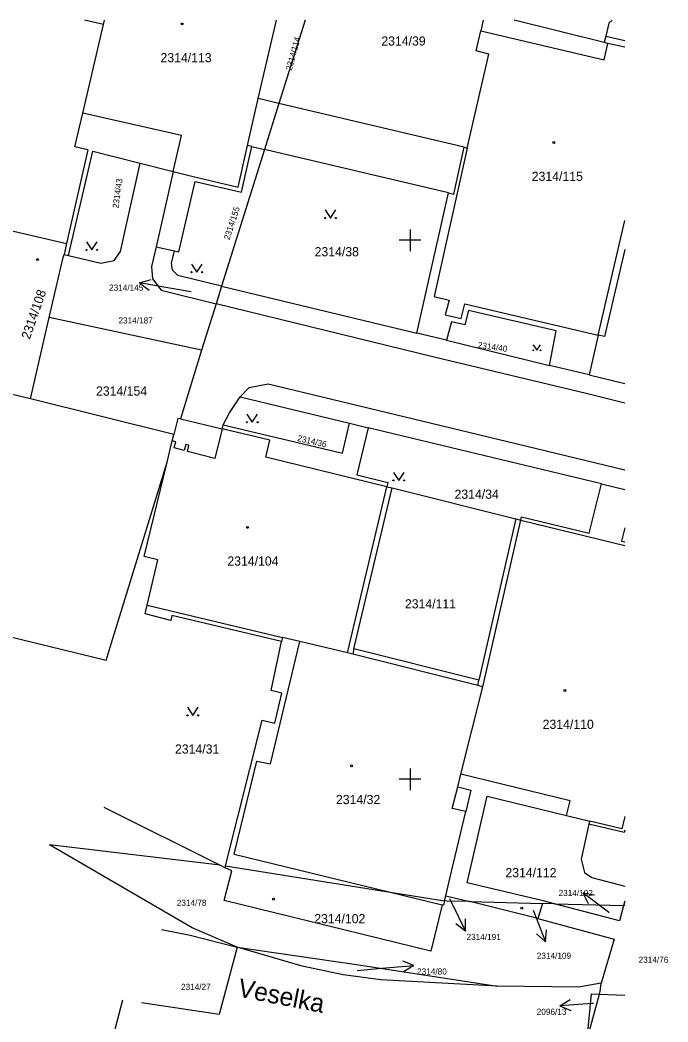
# Model space of a CAD drawing. Extents: x -599866 to -590076, y -1178039 to -1154526.
# Drawn here: x -599586.2 to -599526.1, y -1154622.5 to -1154529.6 of the extents above; entities that cross this region are included whole.
import ezdxf

# ---------------------------------------------------------------- set-up
doc = ezdxf.new("R2010")
doc.units = 0
doc.layers.add('KN', color=7, linetype='Continuous')
doc.layers.add('Vrstva 5', color=7, linetype='Continuous')

msp = doc.modelspace()

# ---------------------------------------------------------------- linework, layer by layer
at = {"layer": 'KN'}
for p, q in [((-599578.44, -1154529.99), (-599580.206, -1154529.575)), ((-599543.211, -1154529.575), (-599543.44, -1154530.57)), ((-599531.85, -1154531.07), (-599531.98, -1154531.65)), ((-599530.082, -1154532.094), (-599531.65, -1154531.74)), ((-599562.17, -1154537.31), (-599564.09, -1154536.86)), ((-599544.98, -1154541.38), (-599562.17, -1154537.31)), ((-599581.09, -1154541.34), (-599580.36, -1154538.2)), ((-599579.88, -1154541.62), (-599581.09, -1154541.34)), ((-599565.94, -1154545.07), (-599565.08, -1154541.22)), ((-599564.69, -1154541.32), (-599563.51, -1154541.59)), ((-599544.69, -1154541.45), (-599547.77, -1154555.23)), ((-599579.88, -1154541.62), (-599581.88, -1154550.3)), ((-599563.51, -1154541.59), (-599567.48, -1154554.25)), ((-599546.44, -1154545.6), (-599563.51, -1154541.59)), ((-599575.04, -1154542.85), (-599571.96, -1154543.63)), ((-599571.96, -1154543.63), (-599573.56, -1154550.62)), ((-599571.96, -1154543.63), (-599570.23, -1154544.06)), ((-599570.23, -1154544.06), (-599565.94, -1154545.07)), ((-599549.37, -1154558.62), (-599546.44, -1154545.6)), ((-599532.54, -1154558.8), (-599530.082, -1154548.169)), ((-599573.56, -1154550.62), (-599571.85, -1154550.99)), ((-599582.1, -1154551.33), (-599581.67, -1154551.43)), ((-599575.095, -1154553.949), (-599574.022, -1154553.63)), ((-599572.14, -1154554.47), (-599575.095, -1154553.949)), ((-599575.095, -1154553.949), (-599574.196, -1154554.616)), ((-599570.3, -1154554.78), (-599572.14, -1154554.47)), ((-599567.48, -1154554.25), (-599567.99, -1154555.9)), ((-599567.48, -1154554.25), (-599549.37, -1154558.62)), ((-599547.77, -1154555.23), (-599546.38, -1154555.56)), ((-599567.99, -1154555.9), (-599569.35, -1154560.2)), ((-599546.38, -1154555.56), (-599546.74, -1154556.93)), ((-599545.27, -1154557.25), (-599544.92, -1154555.9)), ((-599544.92, -1154555.9), (-599532.54, -1154558.8)), ((-599585.22, -1154564.72), (-599583.47, -1154557.16)), ((-599569.35, -1154560.2), (-599583.47, -1154557.16)), ((-599546.74, -1154556.93), (-599545.27, -1154557.25)), ((-599546.63, -1154559.28), (-599549.37, -1154558.62)), ((-599546.63, -1154559.28), (-599537.06, -1154561.61)), ((-599569.35, -1154560.2), (-599571.31, -1154566.58)), ((-599533.39, -1154562.49), (-599537.06, -1154561.61)), ((-599565.76, -1154564.52), (-599555.62, -1154566.96)), ((-599571.91, -1154568.01), (-599585.22, -1154564.72)), ((-599567.43, -1154567.5), (-599568.1, -1154570.23)), ((-599563.01, -1154568.55), (-599567.43, -1154567.5)), ((-599555.62, -1154566.96), (-599553.88, -1154567.39)), ((-599532.25, -1154572.59), (-599553.88, -1154567.39)), ((-599571.73, -1154568.69), (-599572.06, -1154568.6)), ((-599571.87, -1154569.27), (-599571.73, -1154568.69)), ((-599570.95, -1154569.5), (-599571.87, -1154569.27)), ((-599570.81, -1154568.94), (-599570.95, -1154569.5)), ((-599570.51, -1154569.02), (-599570.81, -1154568.94)), ((-599570.65, -1154569.6), (-599570.51, -1154569.02)), ((-599563.39, -1154570.11), (-599563.01, -1154568.55)), ((-599568.1, -1154570.23), (-599570.65, -1154569.6)), ((-599552.16, -1154572.86), (-599563.39, -1154570.11)), ((-599555.81, -1154588.28), (-599552.16, -1154572.86)), ((-599555.2, -1154587.91), (-599551.67, -1154572.98)), ((-599551.67, -1154572.98), (-599540.2, -1154575.83)), ((-599532.25, -1154572.59), (-599530.082, -1154573.112)), ((-599540.2, -1154575.83), (-599543.61, -1154590.81)), ((-599543.24, -1154591.41), (-599539.72, -1154575.95)), ((-599539.72, -1154575.95), (-599530.082, -1154578.327)), ((-599574.4, -1154583.84), (-599561.84, -1154586.84)), ((-599562.95, -1154598.56), (-599560.21, -1154587.23)), ((-599543.61, -1154590.81), (-599555.2, -1154587.91)), ((-599543.72, -1154591.29), (-599555.32, -1154588.4)), ((-599566.31, -1154606.95), (-599564.2, -1154598.31)), ((-599564.2, -1154598.31), (-599562.95, -1154598.56)), ((-599545.58, -1154600.71), (-599545.28, -1154599.52)), ((-599546.08, -1154602.7), (-599545.58, -1154600.71)), ((-599545.58, -1154600.71), (-599544.35, -1154601)), ((-599544.35, -1154601), (-599544.84, -1154602.99)), ((-599578.41, -1154602.57), (-599567.6, -1154607.98)), ((-599544.84, -1154602.99), (-599546.08, -1154602.7)), ((-599546.31, -1154609.2), (-599544.84, -1154602.99)), ((-599530.082, -1154603.45), (-599530.36, -1154604.59)), ((-599530.36, -1154604.59), (-599533.33, -1154603.87)), ((-599567.6, -1154607.98), (-599583.46, -1154606.09)), ((-599566.31, -1154606.95), (-599551.84, -1154610.46)), ((-599567.6, -1154607.98), (-599567.16, -1154608.2)), ((-599567.16, -1154608.2), (-599567.12, -1154608.04)), ((-599546.68, -1154610.8), (-599546.31, -1154609.2)), ((-599551.84, -1154610.46), (-599547.01, -1154611.63)), ((-599546.34, -1154611.07), (-599546.18, -1154611.38)), ((-599531.58, -1154612.33), (-599533.977, -1154610.524)), ((-599533.977, -1154610.524), (-599532.876, -1154610.727)), ((-599533.977, -1154610.524), (-599533.478, -1154611.527)), ((-599546.18, -1154611.38), (-599544.864, -1154614.077)), ((-599544.46, -1154611.34), (-599537.71, -1154611.52)), ((-599538.14, -1154612.91), (-599544.46, -1154611.34)), ((-599537.71, -1154611.52), (-599538.14, -1154612.91)), ((-599536.61, -1154611.55), (-599537.71, -1154611.52)), ((-599536.61, -1154611.55), (-599530.19, -1154611.71)), ((-599530.082, -1154611.312), (-599530.19, -1154611.71)), ((-599530.082, -1154611.713), (-599530.19, -1154611.71)), ((-599544.864, -1154614.077), (-599544.853, -1154612.958)), ((-599538.58, -1154612.13), (-599538.52, -1154612.28)), ((-599538.52, -1154612.28), (-599537.445, -1154615.082)), ((-599531.52, -1154612.38), (-599531.58, -1154612.33)), ((-599544.864, -1154614.077), (-599545.754, -1154613.397)), ((-599537.445, -1154615.082), (-599537.336, -1154613.967)), ((-599537.445, -1154615.082), (-599538.271, -1154614.326)), ((-599554.92, -1154617.74), (-599552.63, -1154617.53)), ((-599552.63, -1154617.53), (-599549.64, -1154617.268)), ((-599549.64, -1154617.268), (-599550.682, -1154616.857)), ((-599549.64, -1154617.268), (-599550.594, -1154617.855)), ((-599532.37, -1154619.69), (-599532.27, -1154618.91)), ((-599536.104, -1154621.009), (-599535.14, -1154620.44)), ((-599533.58, -1154624.09), (-599533.17, -1154619.91)), ((-599533.58, -1154624.09), (-599532.44, -1154619.94)), ((-599533.17, -1154619.91), (-599532.44, -1154619.94)), ((-599532.44, -1154619.94), (-599532.37, -1154619.69)), ((-599532.44, -1154619.94), (-599530.082, -1154620.037)), ((-599533.11, -1154620.8), (-599536.104, -1154621.009)), ((-599536.104, -1154621.009), (-599535.07, -1154621.439)), ((-599532.99, -1154620.79), (-599533.11, -1154620.8))]:
    msp.add_line(p, q, dxfattribs=at)
for points in [[(-599571.96, -1154543.63), (-599571.19, -1154540.29), (-599580.36, -1154538.2), (-599578.44, -1154529.99), (-599578.348, -1154529.575)], [(-599564.69, -1154541.32), (-599565.08, -1154541.22), (-599564.09, -1154536.86), (-599562.387, -1154529.575)], [(-599559.74, -1154529.575), (-599562.17, -1154537.31), (-599563.51, -1154541.59)], [(-599531.98, -1154531.65), (-599540.34, -1154529.58), (-599540.339, -1154529.575)], [(-599531.235, -1154529.575), (-599531.57, -1154529.88), (-599531.85, -1154531.07)], [(-599546.44, -1154545.6), (-599545.95, -1154545.72), (-599544.98, -1154541.38), (-599544.69, -1154541.45), (-599542.69, -1154532.74), (-599543.87, -1154532.43), (-599543.44, -1154530.57), (-599532, -1154533.28), (-599531.65, -1154531.74), (-599531.98, -1154531.65)], [(-599531.85, -1154531.07), (-599530.082, -1154531.472)], [(-599571.85, -1154550.99), (-599571.46, -1154551.08), (-599569.93, -1154544.54), (-599565.64, -1154545.54), (-599564.69, -1154541.32)], [(-599581.67, -1154551.43), (-599579.44, -1154541.73), (-599575.04, -1154542.85)], [(-599581.67, -1154551.43), (-599578.68, -1154552.13), (-599577.45, -1154551.87), (-599576.85, -1154551.03), (-599575.04, -1154542.85)], [(-599557.88, -1154547.19), (-599557.38, -1154547.94), (-599556.88, -1154547.19)], [(-599588.02, -1154550.21), (-599587.72, -1154548.93), (-599581.88, -1154550.3), (-599582.1, -1154551.33)], [(-599580.02, -1154550.15), (-599579.52, -1154550.9), (-599579.02, -1154550.15)], [(-599573.56, -1154550.62), (-599573.97, -1154552.45), (-599573.88, -1154553.58), (-599573.09, -1154554.64), (-599567.99, -1154555.9)], [(-599583.47, -1154557.16), (-599582.18, -1154551.59), (-599582.1, -1154551.33)], [(-599567.48, -1154554.25), (-599571.53, -1154553.27), (-599572.05, -1154552.78), (-599572.12, -1154552.14), (-599571.85, -1154550.99)], [(-599530.082, -1154550.846), (-599531.95, -1154558.93), (-599532.54, -1154558.8), (-599533.39, -1154562.49)], [(-599570.28, -1154552.21), (-599569.78, -1154552.96), (-599569.28, -1154552.21)], [(-599530.082, -1154565.101), (-599533.67, -1154564.23), (-599547.76, -1154560.86), (-599567.99, -1154555.9)], [(-599537.06, -1154561.61), (-599536.43, -1154558.4), (-599544.57, -1154556.51), (-599544.91, -1154557.86), (-599546.17, -1154557.57), (-599546.63, -1154559.28)], [(-599538.565, -1154559.707), (-599538.23, -1154560.21), (-599537.895, -1154559.707)], [(-599533.39, -1154562.49), (-599530.082, -1154563.287)], [(-599578.2, -1154588.98), (-599595.57, -1154584.75), (-599590.49, -1154563.45)], [(-599585.22, -1154564.72), (-599588.77, -1154563.87), (-599590.49, -1154563.45)], [(-599565.76, -1154564.52), (-599564.93, -1154563.65), (-599563.16, -1154563.32), (-599545.44, -1154567.59), (-599530.082, -1154571.309)], [(-599567.34, -1154567.11), (-599566.75, -1154566.01), (-599565.76, -1154564.52)], [(-599571.31, -1154566.58), (-599571.55, -1154566.52), (-599571.91, -1154568.01)], [(-599565.14, -1154566.13), (-599564.64, -1154566.88), (-599564.14, -1154566.13)], [(-599571.31, -1154566.58), (-599567.43, -1154567.5), (-599567.34, -1154567.11)], [(-599567.34, -1154567.11), (-599556.28, -1154569.76), (-599555.62, -1154566.96)], [(-599553.88, -1154567.39), (-599554.93, -1154571.77), (-599552.06, -1154572.47), (-599552.16, -1154572.86), (-599551.67, -1154572.98)], [(-599572.54, -1154570.58), (-599572.06, -1154568.6), (-599571.91, -1154568.01)], [(-599578.2, -1154588.98), (-599577.82, -1154587.73), (-599572.54, -1154570.58)], [(-599574.58, -1154584.66), (-599574.4, -1154583.84), (-599573.41, -1154579.63), (-599574.67, -1154579.32), (-599572.54, -1154570.58)], [(-599551.55, -1154571.529), (-599551.05, -1154572.28), (-599550.55, -1154571.529)], [(-599540.2, -1154575.83), (-599539.72, -1154575.95), (-599539.65, -1154575.66), (-599533.38, -1154577.18), (-599532.25, -1154572.59)], [(-599530.082, -1154576.667), (-599530.4, -1154577.9), (-599530.082, -1154577.98)], [(-599561.93, -1154587.23), (-599572.09, -1154584.8), (-599572.2, -1154585.28), (-599574.58, -1154584.66)], [(-599555.2, -1154587.91), (-599555.32, -1154588.4), (-599555.81, -1154588.28), (-599560.21, -1154587.23), (-599561.84, -1154586.84), (-599561.93, -1154587.23)], [(-599567.12, -1154608.04), (-599563.73, -1154594.52), (-599562.55, -1154594.79), (-599561.88, -1154592.02), (-599562.89, -1154591.75), (-599561.93, -1154587.23)], [(-599535.48, -1154603.35), (-599535.15, -1154601.99), (-599545.28, -1154599.52), (-599543.24, -1154591.41), (-599543.72, -1154591.29), (-599543.61, -1154590.81)], [(-599570.65, -1154593.319), (-599570.15, -1154594.07), (-599569.65, -1154593.319)], [(-599536.61, -1154611.55), (-599537.64, -1154611.28), (-599544.7, -1154609.59), (-599542.85, -1154601.58), (-599535.48, -1154603.35)], [(-599535.48, -1154603.35), (-599533.33, -1154603.87), (-599533.4, -1154604.16)], [(-599533.4, -1154604.16), (-599534.13, -1154607.41), (-599533.83, -1154608.66), (-599533.15, -1154609.11), (-599530.082, -1154609.917)], [(-599530.082, -1154604.713), (-599530.14, -1154604.95), (-599533.4, -1154604.16)], [(-599566.04, -1154615.56), (-599570.21, -1154613.78), (-599583.46, -1154606.09)], [(-599546.79, -1154611.26), (-599546.89, -1154611.66), (-599547.01, -1154611.63), (-599548.08, -1154615.94), (-599567.23, -1154611.23), (-599566.53, -1154608.48), (-599567.16, -1154608.2)], [(-599567.12, -1154608.04), (-599551.84, -1154610.46), (-599546.79, -1154611.26)], [(-599546.79, -1154611.26), (-599546.68, -1154610.8), (-599544.46, -1154611.34)], [(-599544.46, -1154611.34), (-599546.57, -1154611.29), (-599546.79, -1154611.26)], [(-599530.19, -1154611.71), (-599530.58, -1154613.12), (-599536.61, -1154611.55)], [(-599538.14, -1154612.91), (-599531.05, -1154614.84), (-599532.27, -1154618.91)], [(-599573.07, -1154613.94), (-599570.39, -1154614.46), (-599566.04, -1154615.56)], [(-599566.04, -1154615.56), (-599567.7, -1154621.83), (-599574.9, -1154620.73)], [(-599566.04, -1154615.56), (-599554.97, -1154617.19), (-599541.92, -1154619.2)], [(-599541.92, -1154619.2), (-599552.71, -1154618.61), (-599556.21, -1154618.14), (-599560.02, -1154617.32), (-599566.04, -1154615.56)], [(-599532.27, -1154618.91), (-599534.38, -1154619.29), (-599541.92, -1154619.2)], [(-599560.85, -1154635.79), (-599579.42, -1154631.08), (-599576.64, -1154620.46)]]:
    msp.add_lwpolyline(points, dxfattribs=at)
for centre, radius in [((-599571.133, -1154529.94), 0.0875), ((-599536.673, -1154540.94), 0.0875), ((-599557.88, -1154547.94), 0.05), ((-599556.88, -1154547.94), 0.05), ((-599580.02, -1154550.9), 0.05), ((-599579.02, -1154550.9), 0.05), ((-599584.553, -1154551.8), 0.0875), ((-599570.28, -1154552.96), 0.05), ((-599569.28, -1154552.96), 0.05), ((-599538.565, -1154560.21), 0.0335), ((-599537.895, -1154560.21), 0.0335), ((-599565.14, -1154566.88), 0.05), ((-599564.14, -1154566.88), 0.05), ((-599551.55, -1154572.28), 0.05), ((-599550.55, -1154572.28), 0.05), ((-599565.073, -1154576.63), 0.0875), ((-599535.653, -1154591.77), 0.0875), ((-599570.65, -1154594.07), 0.05), ((-599569.65, -1154594.07), 0.05), ((-599555.433, -1154598.75), 0.0875), ((-599562.673, -1154611.11), 0.0875), ((-599539.633, -1154611.95), 0.0875)]:
    msp.add_circle(centre, radius, dxfattribs=at)
at = {"layer": 'Vrstva 5'}
for p, q in [((-599550, -1154549), (-599550, -1154551)), ((-599549, -1154550), (-599551, -1154550)), ((-599550, -1154599), (-599550, -1154601)), ((-599549, -1154600), (-599551, -1154600))]:
    msp.add_line(p, q, dxfattribs=at)

# ---------------------------------------------------------------- texts
at = {"layer": 'KN'}
for s, height, rotation, p in [('2314/114', 0.57, 75, (-599560.986, -1154534.302)), ('2314/43', 0.57, 82, (-599577.053, -1154547.054)), ('2314/155', 0.57, 72, (-599566.759, -1154550.02)), ('2314/108', 0.85, 71, (-599585.283, -1154559.249)), ('2314/40', 0.57, 352, (-599543.744, -1154559.983)), ('2314/36', 0.57, 347, (-599560.497, -1154568.611)), ('Veselka', 1.7, 349, (-599566.065, -1154620.132))]:
    msp.add_text(s, height=height, rotation=rotation, dxfattribs=at).set_placement(p)
for s, height, p in [('2314/39', 0.85, (-599552.662, -1154531.94)), ('2314/113', 0.85, (-599573.148, -1154533.49)), ('2314/115', 0.85, (-599538.708, -1154544.49)), ('2314/38', 0.85, (-599558.852, -1154551.49)), ('2314/145', 0.57, (-599577.92, -1154554.68)), ('2314/187', 0.57, (-599577.05, -1154557.72)), ('2314/154', 0.85, (-599579.134, -1154564.41)), ('2314/34', 0.85, (-599545.872, -1154573.98)), ('2314/104', 0.85, (-599566.944, -1154580.18)), ('2314/111', 0.85, (-599550.475, -1154584.15)), ('2314/110', 0.85, (-599537.698, -1154595.32)), ('2314/31', 0.85, (-599571.806, -1154597.62)), ('2314/32', 0.85, (-599556.875, -1154602.3)), ('2314/112', 0.85, (-599541.154, -1154609.08)), ('2314/192', 0.57, (-599536.222, -1154610.83)), ('2314/78', 0.57, (-599571.639, -1154611.74)), ('2314/102', 0.85, (-599558.887, -1154613.35)), ('2314/191', 0.57, (-599544.76, -1154614.909)), ('2314/109', 0.57, (-599538.24, -1154616.649)), ('2314/76', 0.57, (-599528.796, -1154617.02)), ('2314/80', 0.57, (-599549.35, -1154618.11)), ('2314/27', 0.57, (-599571.251, -1154619.54)), ('2096/13', 0.57, (-599538.248, -1154621.849))]:
    msp.add_text(s, height=height, dxfattribs=at).set_placement(p)

doc.saveas('drawing.dxf')
